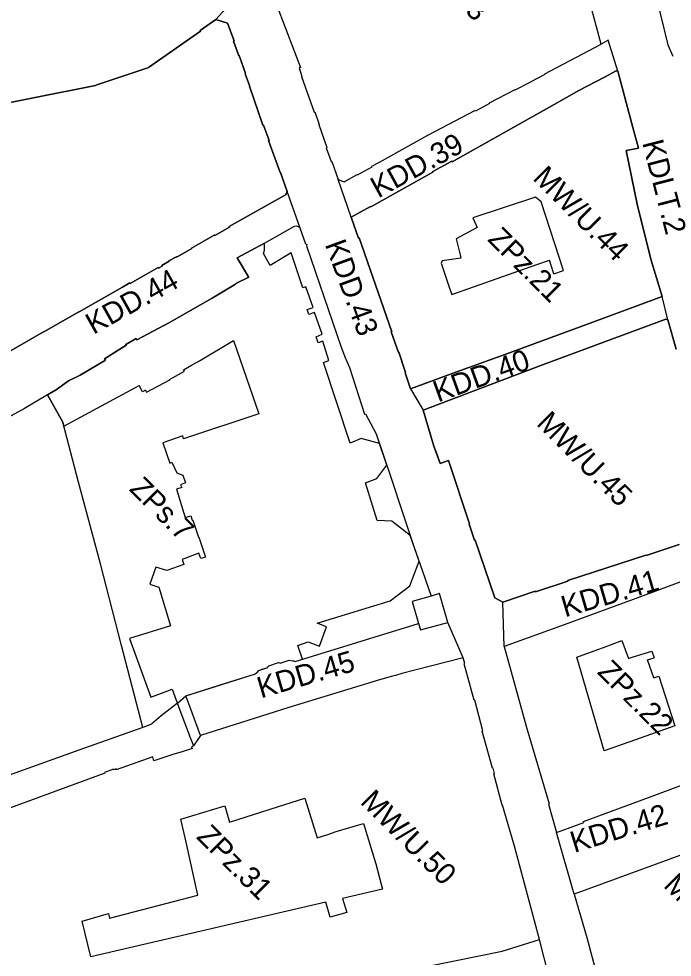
# Model space of a CAD drawing. Extents: x 7423835 to 7425280, y 5546086 to 5547600.
# Drawn here: x 7424089 to 7424273.1, y 5546340.4 to 5546605 of the extents above; entities that cross this region are included whole.
import ezdxf

# ---------------------------------------------------------------- set-up
doc = ezdxf.new("R2010")
doc.units = 0
for name, color, linetype in [('linie rozgraniczające', 7, 'Continuous'), ('nieprzekraczalne linie zabudowy', 7, 'Continuous'), ('obowiazujace linie zabudowy', 7, 'Continuous'), ('przeznaczenia terenów', 7, 'Continuous')]:
    doc.layers.add(name, color=color, linetype=linetype)

msp = doc.modelspace()

# ---------------------------------------------------------------- linework, layer by layer
at = {"layer": 'linie rozgraniczające'}
for p, q in [((7424144.53, 5546604.8), (7424157.55, 5546619.31)), ((7424182.63, 5546549.08), (7424178.96, 5546559.74)), ((7424169.85, 5546541.46), (7424164.64, 5546556.36)), ((7424236.16, 5546553.45), (7424234.55, 5546554.68)), ((7424271.82, 5546520.1), (7424270.28, 5546526.75)), ((7424199.35, 5546500.72), (7424202.88, 5546494.68)), ((7424225.71, 5546428.05), (7424225.41, 5546440.54)), ((7424214.22, 5546424.87), (7424209.83, 5546434.83)), ((7424267.87, 5546419.18), (7424269.29, 5546419.67)), ((7424133.68, 5546412.04), (7424136.07, 5546414.16)), ((7424140.22, 5546402.93), (7424138.23, 5546400.01)), ((7424245.49, 5546358.22), (7424240.49, 5546375.59)), ((7424109.26, 5546340.55), (7424106.89, 5546350.55))]:
    msp.add_line(p, q, dxfattribs=at)
for points in [[(7424264.54, 5546627.07), (7424265.35, 5546624.27), (7424271.84, 5546597.69), (7424273.24, 5546594.48)], [(7424157.55, 5546619.31), (7424159.67, 5546613.74), (7424159.81, 5546613.79), (7424168.34, 5546591.3), (7424168.02, 5546591.18), (7424168.78, 5546588.78), (7424168.69, 5546588.75), (7424172.21, 5546578.7), (7424172.36, 5546578.77), (7424173.58, 5546575.25), (7424173.51, 5546575.17), (7424175.76, 5546568.72), (7424175.62, 5546568.67), (7424177, 5546564.76), (7424177.16, 5546564.8), (7424178.96, 5546559.74)], [(7424178.96, 5546559.74), (7424180.68, 5546559.08), (7424184.35, 5546561.14), (7424184.44, 5546561), (7424188.51, 5546563.29), (7424188.43, 5546563.42), (7424190.58, 5546564.56), (7424204.28, 5546572.23), (7424217.64, 5546579.23), (7424217.72, 5546579.1), (7424221.67, 5546581.19), (7424221.62, 5546581.33), (7424228.8, 5546585.11), (7424228.88, 5546584.99), (7424233.21, 5546587.27), (7424233.39, 5546587.33), (7424237.26, 5546589.38), (7424237.2, 5546589.49), (7424253.09, 5546597.9), (7424248.43, 5546615.1)], [(7424007.92, 5546566.13), (7424007.92, 5546566.13), (7424012.08, 5546566.94), (7424012.12, 5546566.8), (7424019.99, 5546568.34), (7424019.98, 5546568.48), (7424024.36, 5546569.34), (7424024.63, 5546569.25), (7424042.46, 5546572.74), (7424065.98, 5546577.41), (7424080.17, 5546580.17), (7424080.29, 5546580.16), (7424093.65, 5546582.86), (7424110.6, 5546586.22), (7424110.68, 5546586.29), (7424125.36, 5546591.15), (7424125.56, 5546591.27), (7424140.15, 5546601.52), (7424140.07, 5546601.67), (7424144.53, 5546604.8)], [(7424144.53, 5546604.8), (7424147.83, 5546603.76), (7424149.65, 5546598.76), (7424149.48, 5546598.67), (7424150.97, 5546594.61), (7424151.09, 5546594.62), (7424152.9, 5546589.6), (7424152.76, 5546589.52), (7424153.95, 5546586.19), (7424153.97, 5546586.05), (7424157.75, 5546575.03), (7424157.94, 5546575.07), (7424159.51, 5546570.72), (7424159.36, 5546570.67), (7424162.59, 5546561.64), (7424162.74, 5546561.72), (7424164.64, 5546556.36), (7424164.49, 5546556.31), (7424164.47, 5546555.97), (7424164.27, 5546555.64), (7424164.32, 5546555.5), (7424148.29, 5546546.42), (7424148.35, 5546546.29), (7424144.24, 5546543.96), (7424144.19, 5546544.06), (7424137.68, 5546540.36), (7424137.75, 5546540.23), (7424133.59, 5546537.89)], [(7424257.73, 5546590.24), (7424255.06, 5546599.03), (7424253.09, 5546597.9)], [(7424257.3, 5546590.34), (7424257.73, 5546590.24), (7424262, 5546574.33), (7424263.55, 5546568.54), (7424260.15, 5546567.88), (7424263.21, 5546552.78), (7424267.05, 5546537.22), (7424270.28, 5546526.75), (7424248.98, 5546518.78), (7424226.24, 5546510.49), (7424211.11, 5546504.99), (7424199.35, 5546500.72), (7424197.84, 5546505.19), (7424197.98, 5546505.3), (7424196.09, 5546511.02), (7424195.99, 5546510.96), (7424193.95, 5546516.73), (7424194.1, 5546516.79), (7424189.5, 5546530), (7424184.89, 5546543.22), (7424184.72, 5546543.16), (7424182.63, 5546549.08)], [(7424182.63, 5546549.08), (7424188.12, 5546552.13), (7424188.18, 5546552.04), (7424205.68, 5546561.79), (7424205.6, 5546561.92), (7424210.96, 5546564.91), (7424211.08, 5546564.7), (7424239.81, 5546580.85), (7424246.79, 5546584.77), (7424254, 5546588.53), (7424257.3, 5546590.34)], [(7424234.55, 5546554.68), (7424216.9, 5546548.91), (7424218.09, 5546546.13), (7424212.23, 5546542.96), (7424213.32, 5546538.46), (7424213.55, 5546537.5)], [(7424239.78, 5546533.09), (7424242.47, 5546534.02), (7424236.16, 5546553.45), (7424236.16, 5546553.45)], [(7424158.18, 5546541.77), (7424166.66, 5546546.56), (7424167.27, 5546546.64), (7424167.74, 5546546.43), (7424167.84, 5546546.39), (7424168.2, 5546546.17)], [(7424123.96, 5546405.23), (7424117.97, 5546428.29), (7424111.98, 5546451.34), (7424105.82, 5546474.41), (7424101.4, 5546491.29), (7424097.06, 5546498.96), (7424099.14, 5546500.2), (7424099.21, 5546500.25), (7424103.02, 5546502.97), (7424106.31, 5546504.55), (7424113.43, 5546508.79), (7424113.19, 5546509.17), (7424119.28, 5546512.98), (7424119.19, 5546513.14), (7424122.08, 5546514.83), (7424122.3, 5546514.49), (7424131.44, 5546519.35), (7424143.47, 5546526.24), (7424150.01, 5546530.23), (7424150.37, 5546530.45), (7424153.77, 5546532.2), (7424153.75, 5546532.23), (7424150.56, 5546537.65), (7424158.18, 5546541.77)], [(7424169.85, 5546541.46), (7424170.16, 5546541.36), (7424170.01, 5546541.03), (7424170.01, 5546541.03), (7424174.92, 5546526.73), (7424179.83, 5546512.42), (7424179.91, 5546512.22), (7424180.88, 5546509.7), (7424182.13, 5546506.66), (7424186.4, 5546493.51), (7424186.7, 5546493.62), (7424189.71, 5546487.96), (7424193.9, 5546475.46), (7424197.12, 5546465.86)], [(7424133.59, 5546537.89), (7424133.42, 5546537.9), (7424131.31, 5546536.76), (7424131.36, 5546536.64), (7424129.28, 5546535.46), (7424129.38, 5546535.28), (7424128.34, 5546534.69), (7424128.23, 5546534.86), (7424120.4, 5546530.42), (7424120.31, 5546530.54), (7424118.19, 5546529.35), (7424106.02, 5546522.38), (7424105.93, 5546522.4), (7424096.21, 5546516.82), (7424095.99, 5546516.73), (7424083.68, 5546509.71)], [(7424213.55, 5546537.5), (7424208.23, 5546536.76), (7424207.99, 5546536.12)], [(7424207.99, 5546536.12), (7424210.28, 5546529.34), (7424210.96, 5546527.32)], [(7424210.96, 5546527.32), (7424234.68, 5546535.62), (7424238.48, 5546536.95)], [(7424239.78, 5546533.09), (7424238.87, 5546535.78), (7424238.48, 5546536.95)], [(7424202.88, 5546494.68), (7424236.57, 5546507.41), (7424271.3, 5546520.29), (7424271.82, 5546520.1), (7424274.2, 5546511.86)], [(7424097.06, 5546498.96), (7424090.64, 5546495.12), (7424084.98, 5546492.05), (7424082.63, 5546490.76), (7424070.3, 5546483.21), (7424044.42, 5546470.01), (7424038.04, 5546466.26), (7424034.35, 5546463.61), (7424022.62, 5546455.76), (7424013.13, 5546449.48), (7424001.74, 5546441.67), (7423990.34, 5546433.85), (7423977.36, 5546427.73)], [(7424210.06, 5546480.46), (7424207.69, 5546479.64), (7424205.96, 5546484.55), (7424202.88, 5546494.68)], [(7424275, 5546456.78), (7424265.73, 5546453.71), (7424265.69, 5546453.83), (7424243.66, 5546446.6), (7424243.69, 5546446.49), (7424234.57, 5546443.47), (7424234.5, 5546443.62), (7424225.41, 5546440.54), (7424223.09, 5546441.71), (7424217.58, 5546458.04), (7424217.41, 5546457.99), (7424215.85, 5546462.53), (7424215.98, 5546462.58), (7424210.06, 5546480.46)], [(7424197.12, 5546465.86), (7424200.34, 5546456.25), (7424202.75, 5546449.25), (7424205.16, 5546442.26)], [(7424240.49, 5546375.59), (7424248.17, 5546378.38), (7424248.08, 5546378.7), (7424268.21, 5546386.13), (7424281.2, 5546390.99), (7424304.94, 5546399.71), (7424306.43, 5546402.78), (7424294.5, 5546443.44), (7424292.01, 5546450.59), (7424292.84, 5546450.88), (7424292.16, 5546453.27), (7424289.77, 5546452.48), (7424289.8, 5546452.37), (7424282.41, 5546449.55), (7424282.47, 5546449.36), (7424280.68, 5546448.76), (7424280.52, 5546449.23), (7424275.85, 5546447.51), (7424276.23, 5546446.57), (7424264.92, 5546442.34), (7424241.57, 5546433.72), (7424225.71, 5546428.05)], [(7424136.07, 5546414.16), (7424155.45, 5546420.21), (7424155.94, 5546420.57), (7424156.08, 5546420.6), (7424156.59, 5546421.29), (7424159.17, 5546422.14), (7424159.1, 5546422.33), (7424159.39, 5546422.42), (7424159.44, 5546422.59), (7424162.15, 5546423.5), (7424162.3, 5546423.4), (7424162.58, 5546423.49), (7424162.66, 5546423.35), (7424165.19, 5546424.22), (7424166.03, 5546423.99), (7424166.18, 5546424.06), (7424166.83, 5546423.76), (7424201.65, 5546434.56), (7424202.18, 5546432.69), (7424209.83, 5546434.83), (7424207.57, 5546442.94), (7424205.16, 5546442.26)], [(7424269.29, 5546419.67), (7424273.84, 5546405.65), (7424262.72, 5546401.71), (7424260.84, 5546401.05), (7424253.87, 5546398.58), (7424246.23, 5546424.99), (7424252.16, 5546427.18), (7424253.74, 5546427.76), (7424258.94, 5546429.68), (7424260.77, 5546424.62), (7424262.06, 5546425.08), (7424267.36, 5546426.7), (7424267.99, 5546424.81)], [(7424225.71, 5546428.05), (7424232.13, 5546404.93), (7424238.38, 5546383.64), (7424238.19, 5546383.59), (7424240.49, 5546375.59)], [(7424197.38, 5546336.47), (7424225.16, 5546342.14), (7424235.68, 5546345.4), (7424228.61, 5546371.72), (7424225.27, 5546383.34), (7424225.2, 5546383.32), (7424222.81, 5546392.14), (7424222.99, 5546392.2), (7424222.61, 5546393.76), (7424222.42, 5546393.71), (7424219.55, 5546404.2), (7424219.69, 5546404.25), (7424217.44, 5546412.93), (7424217.28, 5546412.88), (7424214.51, 5546423.19), (7424214.69, 5546423.23), (7424214.22, 5546424.87), (7424200.57, 5546421.32), (7424196.94, 5546420.44), (7424195.09, 5546419.88), (7424194.28, 5546419.63), (7424190.63, 5546418.63), (7424165.07, 5546410.84), (7424140.22, 5546402.93)], [(7424267.87, 5546419.18), (7424266.13, 5546424.24), (7424267.99, 5546424.81)], [(7424133.68, 5546412.04), (7424129.13, 5546408.5), (7424126.52, 5546406.23), (7424126.36, 5546406.09), (7424123.96, 5546405.23)], [(7424123.96, 5546405.23), (7424123.96, 5546405.23), (7424105.94, 5546398.77), (7424087.91, 5546392.31), (7424065.35, 5546384.38), (7424042.79, 5546376.46), (7424024.48, 5546370.04), (7424000.69, 5546362.42), (7423972.84, 5546352.13)], [(7424138.23, 5546400.01), (7424137.62, 5546399.74), (7424137.83, 5546399.27), (7424135.32, 5546398.4), (7424132.36, 5546397.54), (7424127.09, 5546395.77), (7424126.8, 5546396.9), (7424116.46, 5546393.29), (7424116.43, 5546393.51), (7424115.71, 5546393.26), (7424115.66, 5546393.41), (7424113.17, 5546392.51), (7424113.2, 5546392.36), (7424077.32, 5546379.16)], [(7424106.89, 5546350.55), (7424114.23, 5546352.78), (7424114.55, 5546351.46), (7424139.46, 5546357.92), (7424136.13, 5546372.88), (7424134.69, 5546379.36), (7424147.06, 5546383.14), (7424148.36, 5546378.46), (7424161.91, 5546382.82), (7424169.55, 5546385.28), (7424173.02, 5546374.09), (7424176.07, 5546375.06), (7424178.39, 5546375.83), (7424186.09, 5546378.16), (7424189.57, 5546366.73), (7424191.13, 5546360.99), (7424191.5, 5546359.65), (7424180.16, 5546357.01), (7424181.38, 5546352.99), (7424176.69, 5546351.7), (7424175.54, 5546355.94), (7424109.25, 5546340.55)], [(7424299.42, 5546377.82), (7424280.16, 5546370.93), (7424245.49, 5546358.22), (7424249.04, 5546346.02), (7424251.62, 5546336.13)], [(7424238.77, 5546333.3), (7424238.31, 5546335.04), (7424235.68, 5546345.4)]]:
    msp.add_lwpolyline(points, dxfattribs=at)
at = {"layer": 'nieprzekraczalne linie zabudowy'}
msp.add_line((7424101.68, 5546490.19), (7424122.91, 5546501.59), dxfattribs=at)
for points in [[(7424168.97, 5546424.43), (7424167.64, 5546428.35), (7424170.54, 5546429.31), (7424173.73, 5546428.17), (7424175.7, 5546433.62), (7424173.02, 5546434.59), (7424193.58, 5546440.92), (7424199.17, 5546445.12), (7424201.77, 5546452.1), (7424199.3, 5546459.36), (7424194.06, 5546463.33), (7424190, 5546463.53), (7424186.66, 5546474.16), (7424189.83, 5546475.4), (7424192.68, 5546479.12), (7424190.61, 5546485.29), (7424185.49, 5546486.64), (7424182.39, 5546485.39), (7424174.82, 5546508.06), (7424176.36, 5546508.65), (7424174.69, 5546514.11), (7424173.36, 5546513.66), (7424172.8, 5546515.38), (7424174.45, 5546516.09), (7424172.27, 5546522.23), (7424170.73, 5546521.68), (7424170.27, 5546523.04), (7424171.89, 5546523.61), (7424169.82, 5546529.43), (7424169.01, 5546529.16), (7424165.71, 5546539), (7424159.8, 5546535.46), (7424157.97, 5546538.8), (7424158.21, 5546539.79), (7424158.18, 5546541.77)], [(7424124.66, 5546500.27), (7424124.97, 5546499.7), (7424131.52, 5546503.21), (7424131.47, 5546503.3), (7424135.66, 5546505.63), (7424135.37, 5546506.08), (7424137.69, 5546507.31), (7424139.91, 5546508.59), (7424149.45, 5546514.33), (7424156.65, 5546493.61), (7424135.43, 5546486.63), (7424135.17, 5546487.45), (7424129.54, 5546485.46), (7424131.56, 5546479.73), (7424132.15, 5546479.99), (7424133.52, 5546476.96), (7424135.21, 5546476.31), (7424135.95, 5546474.15), (7424134.6, 5546473.58), (7424134.89, 5546472.87), (7424133.42, 5546472.42), (7424135.88, 5546464.4), (7424137.48, 5546464.85), (7424137.81, 5546463.61), (7424138.02, 5546463.68), (7424139.62, 5546458.88), (7424139.62, 5546458.88), (7424139.81, 5546458.56), (7424139.81, 5546458.56), (7424141.58, 5546453.26), (7424141.58, 5546453.26), (7424141.58, 5546453.26)], [(7424124.66, 5546500.27), (7424123.88, 5546499.84), (7424122.91, 5546501.59)], [(7424141.58, 5546453.26), (7424140.25, 5546452.8), (7424139.69, 5546454.39), (7424135.07, 5546452.52), (7424135.52, 5546451.11), (7424130.66, 5546449.44), (7424127.56, 5546450.41), (7424125.92, 5546445.58), (7424128.49, 5546444.75), (7424131.71, 5546433.88), (7424120.23, 5546430.26), (7424126.2, 5546413.75), (7424132.22, 5546415.96)], [(7424155.94, 5546420.57), (7424156.08, 5546420.6), (7424156.59, 5546421.29), (7424157.88, 5546421.71), (7424159.17, 5546422.14), (7424159.1, 5546422.33), (7424159.39, 5546422.42), (7424159.44, 5546422.59), (7424162.15, 5546423.5), (7424162.3, 5546423.4), (7424162.58, 5546423.49), (7424162.66, 5546423.35), (7424165.19, 5546424.22), (7424166.03, 5546423.99), (7424166.18, 5546424.06)], [(7424136.07, 5546414.16), (7424145.76, 5546417.19), (7424155.45, 5546420.21)]]:
    msp.add_lwpolyline(points, dxfattribs=at)
at = {"layer": 'obowiazujace linie zabudowy'}
for points in [[(7424157.55, 5546619.31), (7424159.67, 5546613.74), (7424159.81, 5546613.79), (7424168.34, 5546591.3), (7424168.02, 5546591.18), (7424168.78, 5546588.78), (7424168.69, 5546588.75), (7424172.21, 5546578.7), (7424172.36, 5546578.77), (7424173.58, 5546575.25), (7424173.51, 5546575.17), (7424175.76, 5546568.72), (7424175.62, 5546568.67), (7424177, 5546564.76), (7424177.16, 5546564.8), (7424178.96, 5546559.74)], [(7424178.96, 5546559.74), (7424180.68, 5546559.08), (7424184.35, 5546561.14), (7424184.44, 5546561), (7424188.51, 5546563.29), (7424188.43, 5546563.42), (7424190.58, 5546564.56), (7424204.28, 5546572.23), (7424217.64, 5546579.23), (7424217.72, 5546579.1), (7424221.67, 5546581.19), (7424221.62, 5546581.33), (7424228.8, 5546585.11), (7424228.88, 5546584.99), (7424233.21, 5546587.27), (7424233.39, 5546587.33), (7424237.26, 5546589.38), (7424237.2, 5546589.49), (7424253.09, 5546597.9), (7424248.43, 5546615.1)], [(7424144.53, 5546604.8), (7424140.07, 5546601.67), (7424140.15, 5546601.52), (7424125.56, 5546591.27), (7424125.36, 5546591.15), (7424110.68, 5546586.29), (7424110.6, 5546586.22), (7424093.65, 5546582.86), (7424080.29, 5546580.16), (7424080.17, 5546580.17), (7424065.98, 5546577.41), (7424042.46, 5546572.74), (7424024.63, 5546569.25), (7424024.36, 5546569.34), (7424019.98, 5546568.48), (7424019.99, 5546568.34), (7424012.12, 5546566.8), (7424012.08, 5546566.94), (7424007.92, 5546566.13), (7424007.92, 5546566.13)], [(7424133.59, 5546537.89), (7424137.75, 5546540.23), (7424137.68, 5546540.36), (7424144.19, 5546544.06), (7424144.24, 5546543.96), (7424148.35, 5546546.29), (7424148.29, 5546546.42), (7424164.32, 5546555.5), (7424164.27, 5546555.64), (7424164.47, 5546555.97), (7424164.49, 5546556.31), (7424164.64, 5546556.36), (7424162.74, 5546561.72), (7424162.59, 5546561.64), (7424159.36, 5546570.67), (7424159.51, 5546570.72), (7424157.94, 5546575.07), (7424157.75, 5546575.03), (7424153.97, 5546586.05), (7424153.95, 5546586.19), (7424152.76, 5546589.52), (7424152.9, 5546589.6), (7424151.09, 5546594.62), (7424150.97, 5546594.61), (7424149.48, 5546598.67), (7424149.65, 5546598.76), (7424147.83, 5546603.76), (7424144.53, 5546604.8)], [(7424257.3, 5546590.34), (7424254, 5546588.53), (7424246.79, 5546584.77), (7424239.81, 5546580.85), (7424211.08, 5546564.7), (7424210.96, 5546564.91), (7424205.6, 5546561.92), (7424205.68, 5546561.79), (7424188.18, 5546552.04), (7424188.12, 5546552.13), (7424182.63, 5546549.08)], [(7424182.63, 5546549.08), (7424184.72, 5546543.16), (7424184.89, 5546543.22), (7424189.5, 5546530), (7424194.1, 5546516.79), (7424193.95, 5546516.73), (7424195.99, 5546510.96), (7424196.09, 5546511.02), (7424197.98, 5546505.3), (7424197.84, 5546505.19), (7424199.35, 5546500.72), (7424211.11, 5546504.99), (7424226.24, 5546510.49), (7424248.98, 5546518.78), (7424270.28, 5546526.75), (7424267.05, 5546537.22), (7424263.21, 5546552.78), (7424260.15, 5546567.88), (7424263.55, 5546568.54), (7424262, 5546574.33), (7424257.73, 5546590.24), (7424257.3, 5546590.34)], [(7424158.18, 5546541.77), (7424150.56, 5546537.65), (7424153.75, 5546532.23), (7424153.77, 5546532.2), (7424150.37, 5546530.45), (7424150.01, 5546530.23), (7424143.47, 5546526.24), (7424131.44, 5546519.35), (7424122.3, 5546514.49), (7424122.08, 5546514.83), (7424119.19, 5546513.14), (7424119.28, 5546512.98), (7424113.19, 5546509.17), (7424113.43, 5546508.79), (7424106.31, 5546504.55), (7424103.02, 5546502.97), (7424099.21, 5546500.25), (7424099.14, 5546500.2), (7424097.06, 5546498.96), (7424101.4, 5546491.29), (7424101.68, 5546490.19)], [(7424083.68, 5546509.71), (7424095.99, 5546516.73), (7424096.21, 5546516.82), (7424105.93, 5546522.4), (7424106.02, 5546522.38), (7424118.19, 5546529.35), (7424120.31, 5546530.54), (7424120.4, 5546530.42), (7424128.23, 5546534.86), (7424128.34, 5546534.69), (7424129.38, 5546535.28), (7424129.28, 5546535.46), (7424131.36, 5546536.64), (7424131.31, 5546536.76), (7424133.42, 5546537.9), (7424133.59, 5546537.89)], [(7424274.2, 5546511.86), (7424271.82, 5546520.1), (7424271.3, 5546520.29), (7424236.57, 5546507.41), (7424202.88, 5546494.68)], [(7424202.88, 5546494.68), (7424204.42, 5546489.62), (7424205.96, 5546484.55), (7424206.83, 5546482.09), (7424207.69, 5546479.64), (7424210.06, 5546480.46)], [(7424210.06, 5546480.46), (7424215.98, 5546462.58), (7424215.85, 5546462.53), (7424217.41, 5546457.99), (7424217.58, 5546458.04), (7424223.09, 5546441.71), (7424225.41, 5546440.54), (7424234.5, 5546443.62), (7424234.57, 5546443.47), (7424243.69, 5546446.49), (7424243.66, 5546446.6), (7424265.69, 5546453.83), (7424265.73, 5546453.71), (7424275, 5546456.78)], [(7424240.49, 5546375.59), (7424248.17, 5546378.38), (7424248.08, 5546378.7), (7424268.21, 5546386.13), (7424281.2, 5546390.99), (7424304.94, 5546399.71), (7424306.43, 5546402.78), (7424294.5, 5546443.44), (7424292.01, 5546450.59), (7424292.84, 5546450.88), (7424292.16, 5546453.27), (7424289.77, 5546452.48), (7424289.8, 5546452.37), (7424282.41, 5546449.55), (7424282.47, 5546449.36), (7424280.68, 5546448.76), (7424280.52, 5546449.23), (7424275.85, 5546447.51), (7424276.23, 5546446.57), (7424264.92, 5546442.34), (7424241.57, 5546433.72), (7424225.71, 5546428.05)], [(7424207.57, 5546442.94), (7424205.16, 5546442.26), (7424199.82, 5546440.76)], [(7424209.83, 5546434.83), (7424207.57, 5546442.94)], [(7424199.82, 5546440.76), (7424201.65, 5546434.56)], [(7424201.65, 5546434.56), (7424202.18, 5546432.69)], [(7424202.18, 5546432.69), (7424209.83, 5546434.83)], [(7424225.71, 5546428.05), (7424232.13, 5546404.93), (7424238.38, 5546383.64), (7424238.19, 5546383.59), (7424240.49, 5546375.59)], [(7424197.38, 5546336.47), (7424225.16, 5546342.14), (7424235.68, 5546345.4), (7424228.61, 5546371.72), (7424225.27, 5546383.34), (7424225.2, 5546383.32), (7424222.81, 5546392.14), (7424222.99, 5546392.2), (7424222.61, 5546393.76), (7424222.42, 5546393.71), (7424219.55, 5546404.2), (7424219.69, 5546404.25), (7424217.44, 5546412.93), (7424217.28, 5546412.88), (7424214.51, 5546423.19), (7424214.69, 5546423.23), (7424214.22, 5546424.87), (7424200.57, 5546421.32), (7424196.94, 5546420.44), (7424195.09, 5546419.88), (7424194.28, 5546419.63), (7424190.63, 5546418.63), (7424165.07, 5546410.84), (7424140.22, 5546402.93)], [(7424132.22, 5546415.96), (7424134.4, 5546410.08), (7424137.27, 5546402.33), (7424138.23, 5546400.01)], [(7424140.22, 5546402.93), (7424137.2, 5546411.11), (7424136.07, 5546414.16)], [(7424138.23, 5546400.01), (7424137.62, 5546399.74), (7424137.83, 5546399.27), (7424135.32, 5546398.4), (7424132.36, 5546397.54), (7424127.09, 5546395.77), (7424126.8, 5546396.9), (7424116.46, 5546393.29), (7424116.43, 5546393.51), (7424115.71, 5546393.26), (7424115.66, 5546393.41), (7424113.17, 5546392.51), (7424113.2, 5546392.36), (7424077.32, 5546379.16)], [(7424299.42, 5546377.82), (7424280.16, 5546370.93), (7424245.49, 5546358.22), (7424249.04, 5546346.02), (7424251.62, 5546336.13)]]:
    msp.add_lwpolyline(points, dxfattribs=at)

# ---------------------------------------------------------------- texts
at = {"layer": 'przeznaczenia terenów'}
for s, rotation, p in [('MW/U.43', 314.9764, (7424194.01, 5546627.58)), ('KDD.39', 28.7965, (7424190.25, 5546554.32)), ('KDLT.2', 284.4891, (7424264.58, 5546570.09)), ('MW/U.44', 314.9764, (7424233.57, 5546559.85)), ('ZPz.21', 314.9764, (7424220.81, 5546542.58)), ('KDD.43', 290.1343, (7424175.17, 5546541.43)), ('KDD.44', 29.1607, (7424110.02, 5546515.87)), ('KDD.40', 19.973, (7424207.09, 5546496.83)), ('MW/U.45', 314.9764, (7424234.58, 5546490.68)), ('ZPs.7', 314.9764, (7424119.88, 5546472.2)), ('KDD.41', 16.3024, (7424242.86, 5546436.23)), ('KDD.45', 16.3565, (7424157.2, 5546413.37)), ('ZPz.22', 314.9764, (7424251.7, 5546420.57)), ('MW/U.50', 314.9764, (7424184.95, 5546383.97)), ('KDD.42', 17.1691, (7424245.48, 5546369.81)), ('ZPz.31', 314.9764, (7424138.81, 5546374.13)), ('MW/U.47', 314.9764, (7424270.36, 5546360.44))]:
    msp.add_text(s, height=6, rotation=rotation, dxfattribs=at).set_placement(p)

doc.saveas('drawing.dxf')
